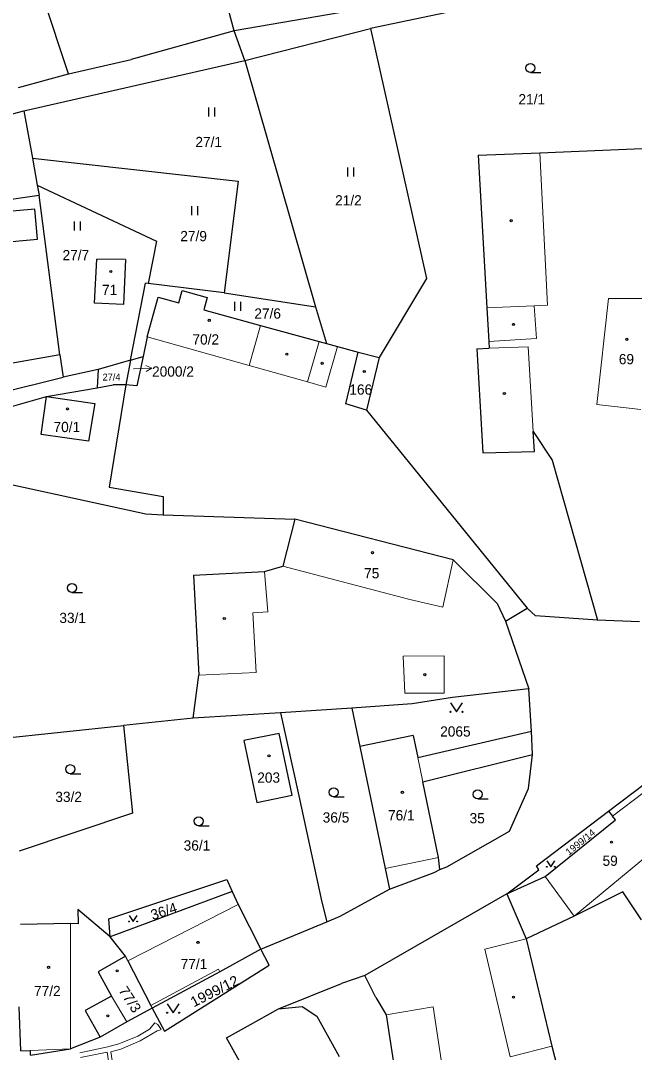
# Model space of a CAD drawing. Extents: x -820420 to -815896, y -1105820 to -1103643.
# Drawn here: x -817636.2 to -817534.2, y -1104729.7 to -1104558.3 of the extents above; entities that cross this region are included whole.
import ezdxf
from ezdxf.enums import TextEntityAlignment as Align

# ---------------------------------------------------------------- set-up
doc = ezdxf.new("R2010")
doc.units = 0
doc.header["$LTSCALE"] = 0.68
for name, color, linetype, lineweight in [('1', 7, 'Continuous', 25), ('13', 7, 'Continuous', 13), ('3', 7, 'Continuous', 25), ('4', 7, 'Continuous', 13), ('5', 7, 'Continuous', 25), ('7', 7, 'Continuous', 13)]:
    doc.layers.add(name, color=color, linetype=linetype, lineweight=lineweight)
doc.layers.add('2', color=7, linetype='Continuous')

msp = doc.modelspace()

# ---------------------------------------------------------------- linework, layer by layer
at = {"layer": '1'}
for p, q in [((-817628.27, -1104567.17), (-817634.49, -1104548.38)), ((-817600.75, -1104560.01), (-817603.37, -1104550.01)), ((-817542.29, -1104552.11), (-817578.07, -1104559.65)), ((-817579.09, -1104556.3), (-817600.75, -1104560.01)), ((-817600.75, -1104560.01), (-817617.84, -1104564.76)), ((-817598.98, -1104564.97), (-817600.75, -1104560.01)), ((-817598.98, -1104564.97), (-817578.07, -1104559.65)), ((-817578.07, -1104559.65), (-817568.76, -1104601.14)), ((-817635.65, -1104573.32), (-817598.98, -1104564.97)), ((-817628.27, -1104567.17), (-817617.84, -1104564.76)), ((-817598.98, -1104564.97), (-817587.2, -1104605.89)), ((-817636.58, -1104569.42), (-817628.27, -1104567.17)), ((-817661.68, -1104580.02), (-817635.65, -1104573.32)), ((-817635.65, -1104573.32), (-817634.24, -1104581.15)), ((-817560.22, -1104580.68), (-817549.95, -1104580.27)), ((-817560.22, -1104580.68), (-817558.75, -1104606.04)), ((-817549.95, -1104580.27), (-817529.32, -1104579.44)), ((-817634.24, -1104581.15), (-817633.43, -1104585.66)), ((-817634.24, -1104581.15), (-817600.04, -1104584.99)), ((-817633.43, -1104585.66), (-817613.64, -1104594.94)), ((-817633.43, -1104585.66), (-817633.13, -1104587.32)), ((-817600.04, -1104584.99), (-817602.39, -1104603.55)), ((-817661, -1104591.22), (-817633.13, -1104587.32)), ((-817629.69, -1104613.81), (-817633.13, -1104587.32)), ((-817633.84, -1104589.64), (-817654.35, -1104591.55)), ((-817633.39, -1104594.63), (-817633.84, -1104589.64)), ((-817653.81, -1104596.51), (-817633.39, -1104594.63)), ((-817613.64, -1104594.94), (-817615.01, -1104602.01)), ((-817623.93, -1104605.28), (-817623.55, -1104597.92)), ((-817618.79, -1104598.02), (-817623.55, -1104597.92)), ((-817618.79, -1104598.02), (-817619.09, -1104605.46)), ((-817568.76, -1104601.14), (-817576.63, -1104614.29)), ((-817617.94, -1104614.71), (-817615.48, -1104601.95)), ((-817615.01, -1104602.01), (-817615.48, -1104601.95)), ((-817602.39, -1104603.55), (-817615.01, -1104602.01)), ((-817609.94, -1104605.19), (-817609.38, -1104603.16)), ((-817609.38, -1104603.16), (-817605.23, -1104604.31)), ((-817615.16, -1104610.82), (-817613.35, -1104604.25)), ((-817613.35, -1104604.25), (-817609.94, -1104605.19)), ((-817605.23, -1104604.31), (-817605.79, -1104606.34)), ((-817602.39, -1104603.55), (-817587.2, -1104605.89)), ((-817619.09, -1104605.46), (-817623.93, -1104605.28)), ((-817605.79, -1104606.34), (-817596.34, -1104608.96)), ((-817587.2, -1104605.89), (-817585.41, -1104611.96)), ((-817558.75, -1104606.04), (-817558.43, -1104611.6)), ((-817596.34, -1104608.96), (-817586.63, -1104611.63)), ((-817615.16, -1104610.82), (-817615.86, -1104614.09)), ((-817586.63, -1104611.63), (-817585.41, -1104611.96)), ((-817558.43, -1104611.6), (-817558.36, -1104612.74)), ((-817585.41, -1104611.96), (-817583.59, -1104612.46)), ((-817583.59, -1104612.46), (-817580.13, -1104613.41)), ((-817582.16, -1104621.99), (-817580.13, -1104613.41)), ((-817580.13, -1104613.41), (-817576.63, -1104614.29)), ((-817560.43, -1104612.82), (-817558.36, -1104612.74)), ((-817560.43, -1104612.82), (-817559.43, -1104630.12)), ((-817629.69, -1104613.81), (-817657.7, -1104618.8)), ((-817629.69, -1104613.81), (-817629.13, -1104617.57)), ((-817617.94, -1104614.71), (-817623.34, -1104616.29)), ((-817617.94, -1104614.71), (-817618.75, -1104618.83)), ((-817617.94, -1104614.71), (-817615.86, -1104614.09)), ((-817615.86, -1104614.09), (-817616.92, -1104619.01)), ((-817576.63, -1104614.29), (-817578.75, -1104623.03)), ((-817623.34, -1104616.29), (-817629.13, -1104617.57)), ((-817623.34, -1104616.29), (-817623.49, -1104619.31)), ((-817656.71, -1104624.28), (-817629.13, -1104617.57)), ((-817631.92, -1104620.74), (-817623.49, -1104619.31)), ((-817623.49, -1104619.31), (-817620.81, -1104618.8)), ((-817618.75, -1104618.83), (-817621.5, -1104635.83)), ((-817618.75, -1104618.83), (-817620.81, -1104618.8)), ((-817616.92, -1104619.01), (-817618.75, -1104618.83)), ((-817642.64, -1104623.82), (-817631.92, -1104620.74)), ((-817632.81, -1104627.07), (-817631.92, -1104620.74)), ((-817631.92, -1104620.74), (-817623.89, -1104621.91)), ((-817623.89, -1104621.91), (-817624.94, -1104628.2)), ((-817578.75, -1104623.03), (-817582.16, -1104621.99)), ((-817578.75, -1104623.03), (-817552.03, -1104655.92)), ((-817624.94, -1104628.2), (-817632.81, -1104627.07)), ((-817550.83, -1104629.88), (-817551.04, -1104626.57)), ((-817551.04, -1104626.57), (-817547.89, -1104631.31)), ((-817559.43, -1104630.12), (-817550.83, -1104629.88)), ((-817659.45, -1104630.67), (-817615.43, -1104640.27)), ((-817547.89, -1104631.31), (-817540.36, -1104657.93)), ((-817621.5, -1104635.83), (-817612.52, -1104637.34)), ((-817612.52, -1104637.34), (-817612.54, -1104640.41)), ((-817615.43, -1104640.27), (-817612.54, -1104640.41)), ((-817612.54, -1104640.41), (-817590.65, -1104641.13)), ((-817590.65, -1104641.13), (-817592.65, -1104648.94)), ((-817564.37, -1104647.88), (-817590.65, -1104641.13)), ((-817595.71, -1104649.81), (-817592.65, -1104648.94)), ((-817564.37, -1104647.88), (-817557.03, -1104655.14)), ((-817607.46, -1104650.41), (-817595.71, -1104649.81)), ((-817607.46, -1104650.41), (-817606.59, -1104667.05)), ((-817557.03, -1104655.14), (-817555.68, -1104658.09)), ((-817555.68, -1104658.09), (-817552.03, -1104655.92)), ((-817550.67, -1104657.18), (-817552.03, -1104655.92)), ((-817540.36, -1104657.93), (-817550.67, -1104657.18)), ((-817533.4, -1104658.16), (-817540.36, -1104657.93)), ((-817555.68, -1104658.09), (-817551.8, -1104669.33)), ((-817607.54, -1104674.19), (-817606.59, -1104667.05)), ((-817551.8, -1104669.33), (-817564.44, -1104670.73)), ((-817551.32, -1104676.31), (-817551.8, -1104669.33)), ((-817564.44, -1104670.73), (-817571.15, -1104671.82)), ((-817593.04, -1104673.29), (-817607.54, -1104674.19)), ((-817581.19, -1104672.5), (-817593.04, -1104673.29)), ((-817593.04, -1104673.29), (-817589.97, -1104687.05)), ((-817571.15, -1104671.82), (-817581.19, -1104672.5)), ((-817581.19, -1104672.5), (-817579.87, -1104678.91)), ((-817607.54, -1104674.19), (-817619.14, -1104675.4)), ((-817640.61, -1104677.65), (-817619.14, -1104675.4)), ((-817619.14, -1104675.4), (-817617.63, -1104689.97)), ((-817593.24, -1104676.7), (-817599.11, -1104677.91)), ((-817591.1, -1104686.98), (-817593.24, -1104676.7)), ((-817570.24, -1104680.69), (-817551.32, -1104676.31)), ((-817551.18, -1104680.22), (-817551.32, -1104676.31)), ((-817599.11, -1104677.91), (-817596.98, -1104688.2)), ((-817571.01, -1104677.03), (-817579.87, -1104678.91)), ((-817571.01, -1104677.03), (-817570.24, -1104680.69)), ((-817579.87, -1104678.91), (-817575.65, -1104699.13)), ((-817569.41, -1104684.73), (-817551.18, -1104680.22)), ((-817551.83, -1104685.84), (-817551.18, -1104680.22)), ((-817538.53, -1104689.62), (-817530.1, -1104683.23)), ((-817566.8, -1104697.3), (-817569.41, -1104684.73)), ((-817596.98, -1104688.2), (-817591.1, -1104686.98)), ((-817589.97, -1104687.05), (-817586.16, -1104704.72)), ((-817554.97, -1104692.92), (-817551.83, -1104685.84)), ((-817617.63, -1104689.97), (-817636.45, -1104696.26)), ((-817550.51, -1104698.7), (-817538.53, -1104689.62)), ((-817538.53, -1104689.62), (-817537.86, -1104690.48)), ((-817537.4, -1104691.07), (-817537.86, -1104690.48)), ((-817549.08, -1104700.48), (-817537.4, -1104691.07)), ((-817565.41, -1104698.85), (-817554.97, -1104692.92)), ((-817566.54, -1104699.32), (-817566.8, -1104697.3)), ((-817566.54, -1104699.32), (-817565.41, -1104698.85)), ((-817550.11, -1104699.35), (-817550.51, -1104698.7)), ((-817575.65, -1104699.13), (-817574.92, -1104702.57)), ((-817574.92, -1104702.57), (-817567.51, -1104699.8)), ((-817567.51, -1104699.8), (-817566.54, -1104699.32)), ((-817555.46, -1104703.34), (-817550.11, -1104699.35)), ((-817555.46, -1104703.34), (-817549.08, -1104700.48)), ((-817621.55, -1104707.49), (-817601.95, -1104700.98)), ((-817601.95, -1104700.98), (-817601.04, -1104702.99)), ((-817601.04, -1104702.99), (-817621.31, -1104710.48)), ((-817601.04, -1104702.99), (-817600.07, -1104705.13)), ((-817583.14, -1104707.05), (-817574.92, -1104702.57)), ((-817555.46, -1104703.34), (-817579, -1104716.89)), ((-817555.46, -1104703.34), (-817552.2, -1104710.82)), ((-817536.14, -1104703), (-817544.22, -1104707.05)), ((-817533.07, -1104707.69), (-817536.14, -1104703)), ((-817621.31, -1104710.48), (-817626.71, -1104705.93)), ((-817626.71, -1104705.93), (-817626.62, -1104708.32)), ((-817600.07, -1104705.13), (-817596.29, -1104712.53)), ((-817586.16, -1104704.72), (-817585.35, -1104708.03)), ((-817621.31, -1104710.48), (-817621.55, -1104707.49)), ((-817585.35, -1104708.03), (-817583.14, -1104707.05)), ((-817544.22, -1104707.05), (-817552.2, -1104710.82)), ((-817627.91, -1104708.27), (-817636.24, -1104708.47)), ((-817626.62, -1104708.32), (-817627.91, -1104708.27)), ((-817596.29, -1104712.53), (-817585.35, -1104708.03)), ((-817618.8, -1104713.71), (-817621.31, -1104710.48)), ((-817552.2, -1104710.82), (-817547.94, -1104728.66)), ((-817596.29, -1104712.53), (-817603.11, -1104716.32)), ((-817594.92, -1104715.22), (-817596.29, -1104712.53)), ((-817618.8, -1104713.71), (-817623.35, -1104716.32)), ((-817618.41, -1104714.48), (-817618.8, -1104713.71)), ((-817618.41, -1104714.48), (-817614.58, -1104721.92)), ((-817612.28, -1104726.14), (-817594.92, -1104715.22)), ((-817623.35, -1104716.32), (-817621.09, -1104720.36)), ((-817603.11, -1104716.32), (-817614.34, -1104722.36)), ((-817579, -1104716.89), (-817582.91, -1104718.24)), ((-817577.17, -1104720.55), (-817579, -1104716.89)), ((-817593.37, -1104722.43), (-817582.91, -1104718.24)), ((-817621.09, -1104720.36), (-817625.47, -1104722.74)), ((-817577.17, -1104720.55), (-817575.5, -1104723.43)), ((-817636.17, -1104729.45), (-817636.47, -1104722.12)), ((-817625.47, -1104722.74), (-817622.99, -1104727.17)), ((-817614.34, -1104722.36), (-817618.55, -1104724.61)), ((-817614.58, -1104721.92), (-817614.34, -1104722.36)), ((-817614.34, -1104722.36), (-817612.28, -1104726.14)), ((-817598.5, -1104725.32), (-817593.37, -1104722.43)), ((-817593.37, -1104722.43), (-817589.43, -1104722.04)), ((-817589.43, -1104722.04), (-817587, -1104723.69)), ((-817618.55, -1104724.61), (-817622.99, -1104727.17)), ((-817587, -1104723.69), (-817583.28, -1104730.35)), ((-817575.5, -1104723.43), (-817572.2, -1104744.84)), ((-817602.03, -1104727.27), (-817598.5, -1104725.32)), ((-817622.99, -1104727.17), (-817627.9, -1104729.11)), ((-817598.99, -1104732.66), (-817602.03, -1104727.27)), ((-817636.17, -1104729.45), (-817634.58, -1104729.38)), ((-817634.56, -1104730.16), (-817634.58, -1104729.38)), ((-817634.56, -1104730.16), (-817627.9, -1104729.11)), ((-817547.94, -1104728.66), (-817543.49, -1104745.73))]:
    msp.add_line(p, q, dxfattribs=at)
at = {"layer": '13'}
for points in [[(-817621.02, -1104731.05), (-817621.23, -1104729.59), (-817619.58, -1104729.13), (-817616.33, -1104727.78), (-817613.51, -1104726.13), (-817613.07, -1104726.01), (-817612.88, -1104725.9), (-817613.41, -1104725.03), (-817613.89, -1104724.8), (-817614.79, -1104725.84), (-817616.73, -1104726.98), (-817619.88, -1104728.27), (-817621.71, -1104728.79), (-817626.36, -1104729.75)], [(-817626.26, -1104730.55), (-817621.83, -1104729.67), (-817621.62, -1104731.11)]]:
    msp.add_lwpolyline(points, dxfattribs=at)
at = {"layer": '3'}
for p, q in [((-817551.513, -1104566.94), (-817549.763, -1104566.94)), ((-817604.941, -1104574.27), (-817604.941, -1104572.77)), ((-817603.94, -1104574.27), (-817603.94, -1104572.77)), ((-817581.861, -1104584.22), (-817581.861, -1104582.72)), ((-817580.86, -1104584.22), (-817580.86, -1104582.72)), ((-817607.741, -1104590.65), (-817607.741, -1104589.15)), ((-817606.74, -1104590.65), (-817606.74, -1104589.15)), ((-817627.251, -1104593.19), (-817627.251, -1104591.69)), ((-817626.25, -1104593.19), (-817626.25, -1104591.69)), ((-817600.631, -1104606.55), (-817600.631, -1104605.05)), ((-817599.63, -1104606.55), (-817599.63, -1104605.05)), ((-817627.683, -1104653.29), (-817625.933, -1104653.29)), ((-817627.963, -1104683.4), (-817626.213, -1104683.4)), ((-817584.203, -1104687.24), (-817582.453, -1104687.24)), ((-817560.273, -1104687.58), (-817558.523, -1104687.58)), ((-817606.643, -1104692.04), (-817604.893, -1104692.04))]:
    msp.add_line(p, q, dxfattribs=at)
for points in [[(-817564.8, -1104671.629), (-817563.8, -1104673.13), (-817562.8, -1104671.629)], [(-817548.8, -1104697.874), (-817548.13, -1104698.88), (-817547.46, -1104697.874)], [(-817618.2, -1104706.934), (-817617.53, -1104707.94), (-817616.86, -1104706.934)], [(-817611.86, -1104721.599), (-817610.86, -1104723.1), (-817609.86, -1104721.599)]]:
    msp.add_lwpolyline(points, dxfattribs=at)
for centre, radius in [((-817551.5129, -1104566.1898), 0.75), ((-817627.6829, -1104652.5398), 0.75), ((-817564.8, -1104673.1295), 0.1), ((-817562.8, -1104673.1295), 0.1), ((-817627.9629, -1104682.6498), 0.75), ((-817584.2029, -1104686.4898), 0.75), ((-817560.2729, -1104686.8298), 0.75), ((-817606.6429, -1104691.2898), 0.75), ((-817548.8, -1104698.8796), 0.067), ((-817547.46, -1104698.8796), 0.067), ((-817618.2, -1104707.9396), 0.067), ((-817616.86, -1104707.9396), 0.067), ((-817611.86, -1104723.0995), 0.1), ((-817609.86, -1104723.0995), 0.1)]:
    msp.add_circle(centre, radius, dxfattribs=at)
at = {"layer": '4'}
for p, q in [((-817549.95, -1104580.27), (-817548.67, -1104605.59)), ((-817540.5, -1104622.09), (-817538.57, -1104604.48)), ((-817538.57, -1104604.48), (-817531.2, -1104604.49)), ((-817550.9, -1104605.69), (-817558.75, -1104606.04)), ((-817596.34, -1104608.96), (-817598.25, -1104615.62)), ((-817598.25, -1104615.62), (-817615.16, -1104610.82)), ((-817550.49, -1104611.14), (-817558.43, -1104611.6)), ((-817583.59, -1104612.46), (-817585.49, -1104619.2)), ((-817558.36, -1104612.74), (-817551.91, -1104612.51)), ((-817551.04, -1104626.57), (-817551.91, -1104612.51)), ((-817585.49, -1104619.2), (-817588.54, -1104618.33)), ((-817540.5, -1104622.09), (-817533.18, -1104622.89)), ((-817571.55, -1104654.49), (-817592.65, -1104648.94)), ((-817564.37, -1104647.88), (-817566.07, -1104655.76)), ((-817595.12, -1104656.54), (-817595.71, -1104649.81)), ((-817566.07, -1104655.76), (-817571.55, -1104654.49)), ((-817597.62, -1104656.67), (-817595.12, -1104656.54)), ((-817597.1, -1104666.57), (-817597.62, -1104656.67)), ((-817572.64, -1104663.86), (-817565.82, -1104663.85)), ((-817565.82, -1104663.85), (-817565.82, -1104670)), ((-817606.59, -1104667.05), (-817597.1, -1104666.57)), ((-817570.24, -1104680.69), (-817569.41, -1104684.73)), ((-817537.86, -1104690.48), (-817532.62, -1104686.49)), ((-817527.44, -1104693.13), (-817544.22, -1104707.05)), ((-817575.65, -1104699.13), (-817566.8, -1104697.3)), ((-817549.08, -1104700.48), (-817544.22, -1104707.05)), ((-817600.07, -1104705.13), (-817618.41, -1104714.48)), ((-817627.9, -1104729.11), (-817627.91, -1104708.27)), ((-817603.35, -1104715.88), (-817614.58, -1104721.92)), ((-817603.11, -1104716.32), (-817603.35, -1104715.88)), ((-817621.09, -1104720.36), (-817618.55, -1104724.61)), ((-817634.58, -1104729.38), (-817627.9, -1104729.11)), ((-817554.86, -1104730.41), (-817547.94, -1104728.66))]:
    msp.add_line(p, q, dxfattribs=at)
for points in [[(-817548.67, -1104605.59), (-817550.9, -1104605.69), (-817550.49, -1104611.14)], [(-817598.25, -1104615.62), (-817588.54, -1104618.33), (-817586.63, -1104611.63)], [(-817565.82, -1104670), (-817572.36, -1104670), (-817572.64, -1104663.86)], [(-817554.86, -1104730.41), (-817559.11, -1104712.53), (-817552.2, -1104710.82)], [(-817575.5, -1104723.43), (-817567.69, -1104722.11), (-817564.38, -1104743.74)]]:
    msp.add_lwpolyline(points, dxfattribs=at)
at = {"layer": '5'}
for centre in [(-817554.7168, -1104591.5492), (-817621.2068, -1104599.9892), (-817604.8668, -1104608.1092), (-817554.3368, -1104608.7792), (-817535.5068, -1104611.2592), (-817591.9868, -1104613.7292), (-817586.1168, -1104615.2492), (-817579.1168, -1104616.5992), (-817555.8468, -1104620.2492), (-817628.4268, -1104622.8192), (-817577.7368, -1104646.6892), (-817602.3668, -1104657.6192), (-817569.0468, -1104666.9492), (-817594.9468, -1104680.4292), (-817572.7868, -1104686.4892), (-817538.0568, -1104694.7792), (-817606.7368, -1104711.4192), (-817631.5568, -1104715.5592), (-817620.1768, -1104716.1492), (-817554.3268, -1104720.5192), (-817621.7268, -1104723.6092)]:
    msp.add_circle(centre, 0.175, dxfattribs=at)
at = {"layer": '7'}
msp.add_line((-817614.381, -1104616.075), (-817615.399, -1104615.61), dxfattribs=at)
msp.add_lwpolyline([(-817617.43, -1104616.18), (-817617.38, -1104616.18), (-817614.381, -1104616.075), (-817615.364, -1104616.611)], dxfattribs=at)

# ---------------------------------------------------------------- texts
at = {"layer": '2'}
for s, height, p in [('21/1', 1.7, (-817551.289, -1104572.235)), ('27/1', 1.7, (-817604.959, -1104579.335)), ('21/2', 1.7, (-817581.749, -1104589.025)), ('27/9', 1.7, (-817607.469, -1104594.965)), ('27/7', 1.7, (-817627.029, -1104598.125)), ('71', 1.7, (-817621.419, -1104603.895)), ('27/6', 1.7, (-817595.169, -1104607.825)), ('70/2', 1.7, (-817605.449, -1104612.125)), ('69', 1.7, (-817535.569, -1104615.405)), ('27/4', 1.14, (-817621.11, -1104618.105)), ('166', 1.7, (-817579.699, -1104620.445)), ('70/1', 1.7, (-817628.529, -1104626.665)), ('75', 1.7, (-817577.879, -1104650.955)), ('33/1', 1.7, (-817627.559, -1104658.375)), ('2065', 1.7, (-817563.98, -1104677.235)), ('203', 1.7, (-817594.999, -1104684.895)), ('33/2', 1.7, (-817628.229, -1104688.095)), ('36/5', 1.7, (-817583.809, -1104691.515)), ('76/1', 1.7, (-817572.959, -1104691.155)), ('35', 1.7, (-817560.359, -1104691.645)), ('36/1', 1.7, (-817606.909, -1104696.165)), ('59', 1.7, (-817538.269, -1104698.705)), ('77/1', 1.7, (-817607.409, -1104715.865)), ('77/2', 1.7, (-817631.769, -1104720.345))]:
    msp.add_text(s, height=height, dxfattribs=at).set_placement(p, align=Align.CENTER)
msp.add_text('2000/2', height=1.7, dxfattribs=at).set_placement((-817614.37, -1104617.455))
at = {"layer": '2', "width": 1.05}
for s, height, rotation, p in [('1999/14', 1.14, 39, (-817542.8677, -1104695.2135)), ('1999/12', 1.7, 27, (-817603.6004, -1104720.2681)), ('77/3', 1.7, 303, (-817618.7526, -1104721.3466))]:
    msp.add_text(s, height=height, rotation=rotation, dxfattribs=at).set_placement(p, align=Align.CENTER)
at = {"layer": '2'}
msp.add_text('36/4', height=1.7, rotation=18, dxfattribs=at).set_placement((-817612.1647, -1104707.05), align=Align.CENTER)

doc.saveas('drawing.dxf')
